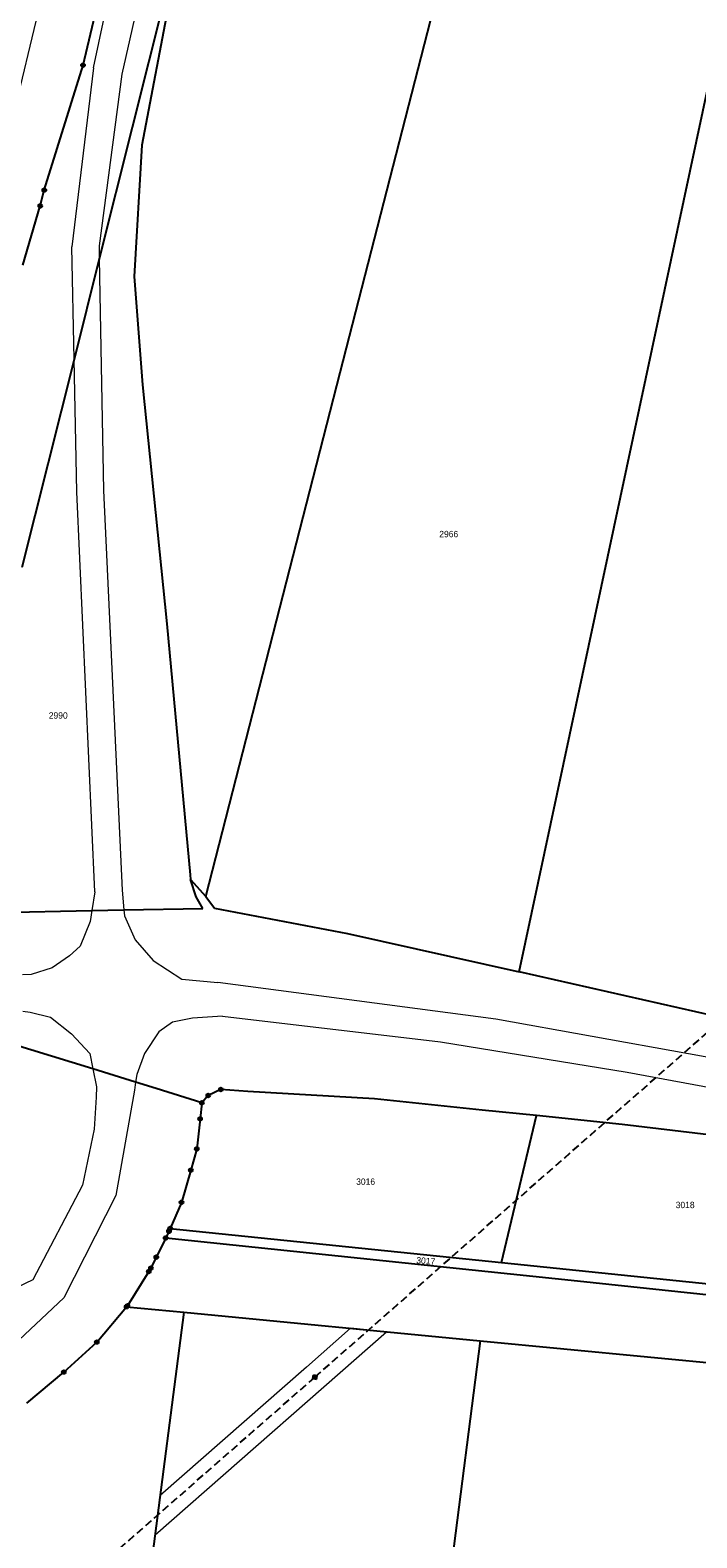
# Model space of a CAD drawing. Extents: x -606517 to -602431, y -1183120 to -1179397.
# Drawn here: x -604805.8 to -604627.6, y -1182528.7 to -1182125.3 of the extents above; entities that cross this region are included whole.
import ezdxf

# ---------------------------------------------------------------- set-up
doc = ezdxf.new("R2010")
doc.units = 0
doc.header["$LTSCALE"] = 0.68
doc.linetypes.add('MEDIUM_DASHED', pattern=[4.5, 3, -1.5])
for name, color, linetype, lineweight in [('1', 7, 'Continuous', 25), ('13', 7, 'Continuous', 13), ('4', 7, 'Continuous', 13), ('6', 7, 'Continuous', 25), ('8', 7, 'Continuous', 25)]:
    doc.layers.add(name, color=color, linetype=linetype, lineweight=lineweight)
doc.layers.add('2', color=7, linetype='Continuous')

msp = doc.modelspace()

# ---------------------------------------------------------------- linework, layer by layer
at = {"layer": '1'}
for p, q in [((-604722.94, -1182216.85), (-604687.02, -1182076.6)), ((-604791.72, -1182134.66), (-604782.46, -1182095.61)), ((-604765.78, -1182100.31), (-604787.38, -1182186.5)), ((-604765.48, -1182100.4), (-604775.96, -1182156.06)), ((-604648.04, -1182250.24), (-604620.95, -1182123.2)), ((-604802.07, -1182168.08), (-604791.72, -1182134.66)), ((-604775.96, -1182156.06), (-604778.06, -1182191.22)), ((-604803.16, -1182172.33), (-604802.07, -1182168.08)), ((-604807.79, -1182188.19), (-604803.16, -1182172.33)), ((-604787.38, -1182186.5), (-604794.11, -1182213.39)), ((-604778.06, -1182191.22), (-604775.78, -1182220.23)), ((-604794.11, -1182213.39), (-604808.07, -1182269.09)), ((-604758.86, -1182357.1), (-604722.94, -1182216.85)), ((-604775.78, -1182220.23), (-604769.29, -1182284.11)), ((-604675.13, -1182377.28), (-604648.04, -1182250.24)), ((-604769.29, -1182284.11), (-604763.08, -1182351.29)), ((-604763.08, -1182351.29), (-604762.97, -1182352.51)), ((-604761.51, -1182357.16), (-604762.97, -1182352.51)), ((-604762.97, -1182352.51), (-604758.86, -1182357.1)), ((-604759.68, -1182360.28), (-604761.51, -1182357.16)), ((-604758.86, -1182357.1), (-604756.6, -1182360.22)), ((-604814.45, -1182361.33), (-604789.32, -1182360.85)), ((-604789.32, -1182360.85), (-604780.77, -1182360.68)), ((-604780.77, -1182360.68), (-604759.68, -1182360.28)), ((-604756.6, -1182360.22), (-604721.02, -1182366.95)), ((-604721.02, -1182366.95), (-604675.13, -1182377.28)), ((-604601.13, -1182393.97), (-604675.13, -1182377.28)), ((-604789.11, -1182403.23), (-604811.16, -1182396.39)), ((-604777.66, -1182406.78), (-604789.11, -1182403.23)), ((-604772.17, -1182408.48), (-604777.66, -1182406.78)), ((-604759.93, -1182412.28), (-604772.17, -1182408.48)), ((-604754.87, -1182408.73), (-604758.24, -1182410.33)), ((-604747.66, -1182409.23), (-604754.87, -1182408.73)), ((-604713.81, -1182411.27), (-604747.66, -1182409.23)), ((-604759.93, -1182412.28), (-604760.42, -1182416.59)), ((-604758.24, -1182410.33), (-604759.93, -1182412.28)), ((-604684.96, -1182414.24), (-604713.81, -1182411.27)), ((-604760.42, -1182416.59), (-604761.3, -1182424.64)), ((-604670.44, -1182415.73), (-604684.96, -1182414.24)), ((-604679.86, -1182455.04), (-604670.44, -1182415.73)), ((-604647.53, -1182418.09), (-604670.44, -1182415.73)), ((-604606.24, -1182423.1), (-604647.53, -1182418.09)), ((-604761.3, -1182424.64), (-604762.89, -1182430.33)), ((-604762.89, -1182430.33), (-604765.39, -1182438.92)), ((-604765.39, -1182438.92), (-604768.42, -1182445.93)), ((-604768.42, -1182445.93), (-604768.74, -1182446.67)), ((-604768.42, -1182445.93), (-604679.86, -1182455.04)), ((-604769.62, -1182448.47), (-604772.13, -1182453.59)), ((-604768.74, -1182446.67), (-604769.62, -1182448.47)), ((-604659.54, -1182460.04), (-604769.62, -1182448.47)), ((-604772.13, -1182453.59), (-604773.56, -1182456.53)), ((-604774.13, -1182457.44), (-604779.85, -1182466.62)), ((-604773.56, -1182456.53), (-604774.13, -1182457.44)), ((-604679.86, -1182455.04), (-604596.72, -1182463.59)), ((-604549.45, -1182471.62), (-604659.54, -1182460.04)), ((-604788.05, -1182476.32), (-604780.06, -1182466.87)), ((-604764.76, -1182468.34), (-604781.97, -1182601.69)), ((-604779.85, -1182466.62), (-604780.06, -1182466.87)), ((-604780.06, -1182466.87), (-604764.76, -1182468.34)), ((-604764.76, -1182468.34), (-604685.5, -1182475.94)), ((-604796.84, -1182484.35), (-604788.05, -1182476.32)), ((-604685.5, -1182475.94), (-604700.64, -1182593.25)), ((-604685.5, -1182475.94), (-604568.08, -1182487.2)), ((-604806.77, -1182492.62), (-604796.84, -1182484.35))]:
    msp.add_line(p, q, dxfattribs=at)
at = {"layer": '13'}
msp.add_lwpolyline([(-604771.09, -1182517.35), (-604772.44, -1182527.86), (-604727.37, -1182488.28), (-604710.6, -1182473.53), (-604720.16, -1182472.62), (-604731.99, -1182483.02)], close=True, dxfattribs=at)
at = {"layer": '4'}
for p, q in [((-604794.45, -1182081.46), (-604811.14, -1182151.18)), ((-604788.9, -1182135.4), (-604780.53, -1182096.1)), ((-604788.9, -1182135.4), (-604794.72, -1182183.29)), ((-604781.36, -1182137.03), (-604787.44, -1182182.96)), ((-604787.44, -1182182.96), (-604787.38, -1182186.5)), ((-604787.38, -1182186.5), (-604786.26, -1182248.48)), ((-604788.53, -1182355.83), (-604793.4, -1182248.8)), ((-604786.26, -1182248.48), (-604781.28, -1182355.44)), ((-604781.28, -1182355.44), (-604780.77, -1182360.68)), ((-604780.77, -1182360.68), (-604780.61, -1182362.27)), ((-604800.01, -1182376.17), (-604805.59, -1182377.92)), ((-604805.59, -1182377.92), (-604807.93, -1182378.05)), ((-604754.47, -1182389.12), (-604696.16, -1182395.94)), ((-604696.16, -1182395.94), (-604646.24, -1182404.1)), ((-604646.24, -1182404.1), (-604436.61, -1182443.22)), ((-604788.15, -1182408.01), (-604788.24, -1182410.75))]:
    msp.add_line(p, q, dxfattribs=at)
for points in [[(-604771.79, -1182094.77), (-604772.6, -1182098.36), (-604781.36, -1182137.03)], [(-604793.4, -1182248.8), (-604794.11, -1182213.39), (-604794.72, -1182183.29)], [(-604788.53, -1182355.83), (-604789.32, -1182360.85), (-604789.78, -1182363.77)], [(-604789.78, -1182363.77), (-604792.47, -1182370.38), (-604795.36, -1182372.96), (-604800.01, -1182376.17)], [(-604780.61, -1182362.27), (-604777.8, -1182368.68), (-604772.99, -1182374.18), (-604765.31, -1182379.25), (-604755.66, -1182380.1)], [(-604604.04, -1182403.79), (-604681.33, -1182389.88), (-604755.66, -1182380.1)], [(-604807.8, -1182387.79), (-604805.89, -1182388), (-604800.43, -1182389.41), (-604794.84, -1182393.83), (-604789.93, -1182399.11)], [(-604754.47, -1182389.12), (-604762.43, -1182389.64), (-604767.81, -1182390.74), (-604771.49, -1182393.31), (-604775.28, -1182399.07), (-604777.36, -1182404.7)], [(-604789.93, -1182399.11), (-604789.11, -1182403.23), (-604788.15, -1182408.01)], [(-604777.36, -1182404.7), (-604777.66, -1182406.78), (-604777.96, -1182408.91)], [(-604777.96, -1182408.91), (-604782.95, -1182437.12), (-604796.84, -1182464.47), (-604819.35, -1182485.58)], [(-604788.24, -1182410.75), (-604788.77, -1182419.35), (-604791.87, -1182434.32)], [(-604791.87, -1182434.32), (-604805.13, -1182459.7), (-604828.46, -1182470.84)]]:
    msp.add_lwpolyline(points, dxfattribs=at)
at = {"layer": '6'}
for p, q in [((-604730.275, -1182486.034), (-604730.067, -1182485.056)), ((-604730.275, -1182486.034), (-604729.295, -1182486.242)), ((-604730.233, -1182485.839), (-604729.254, -1182486.047)), ((-604730.191, -1182485.643), (-604729.212, -1182485.851)), ((-604730.15, -1182485.447), (-604729.171, -1182485.655)), ((-604730.108, -1182485.252), (-604729.129, -1182485.46)), ((-604730.078, -1182486.076), (-604729.87, -1182485.098)), ((-604730.067, -1182485.056), (-604729.087, -1182485.264)), ((-604729.883, -1182486.117), (-604729.675, -1182485.139)), ((-604729.687, -1182486.159), (-604729.479, -1182485.181)), ((-604729.492, -1182486.201), (-604729.284, -1182485.222)), ((-604729.295, -1182486.242), (-604729.087, -1182485.264))]:
    msp.add_line(p, q, dxfattribs=at)
at = {"layer": '6', "linetype": 'MEDIUM_DASHED'}
msp.add_lwpolyline([(-605015.62, -1182869.31), (-604910.62, -1182644.53), (-604729.68, -1182485.65), (-604552.48, -1182329.87)], dxfattribs=at)
at = {"layer": '8'}
for centre, radius in [((-604791.72, -1182134.6599), 0.5), ((-604791.72, -1182134.6599), 0.0303), ((-604802.07, -1182168.0799), 0.5), ((-604802.07, -1182168.0799), 0.0303), ((-604803.16, -1182172.3299), 0.5), ((-604803.16, -1182172.3299), 0.0303), ((-604754.87, -1182408.7299), 0.5), ((-604754.87, -1182408.7299), 0.0303), ((-604759.93, -1182412.2799), 0.5), ((-604759.93, -1182412.2799), 0.0303), ((-604758.24, -1182410.3299), 0.5), ((-604758.24, -1182410.3299), 0.0303), ((-604760.42, -1182416.5899), 0.5), ((-604760.42, -1182416.5899), 0.0303), ((-604761.3, -1182424.6399), 0.5), ((-604761.3, -1182424.6399), 0.0303), ((-604762.89, -1182430.3299), 0.5), ((-604762.89, -1182430.3299), 0.0303), ((-604765.39, -1182438.9199), 0.5), ((-604765.39, -1182438.9199), 0.0303), ((-604768.42, -1182445.9299), 0.5), ((-604768.42, -1182445.9299), 0.0303), ((-604769.62, -1182448.4699), 0.5), ((-604769.62, -1182448.4699), 0.0303), ((-604768.74, -1182446.6699), 0.5), ((-604768.74, -1182446.6699), 0.0303), ((-604772.13, -1182453.5899), 0.5), ((-604772.13, -1182453.5899), 0.0303), ((-604774.13, -1182457.4399), 0.5), ((-604774.13, -1182457.4399), 0.0303), ((-604773.56, -1182456.5299), 0.5), ((-604773.56, -1182456.5299), 0.0303), ((-604779.85, -1182466.6199), 0.5), ((-604780.06, -1182466.8699), 0.5), ((-604780.06, -1182466.8699), 0.0303), ((-604779.85, -1182466.6199), 0.0303), ((-604788.05, -1182476.3199), 0.5), ((-604788.05, -1182476.3199), 0.0303), ((-604796.84, -1182484.3499), 0.5), ((-604796.84, -1182484.3499), 0.0303)]:
    msp.add_circle(centre, radius, dxfattribs=at)

# ---------------------------------------------------------------- texts
at = {"layer": '2'}
for s, p in [('2966', (-604696.47, -1182260.965)), ('2990', (-604800.87, -1182309.505)), ('3016', (-604718.69, -1182434.235)), ('3018', (-604633.26, -1182440.475))]:
    msp.add_text(s, height=1.7, dxfattribs=at).set_placement(p)
msp.add_text('3017', height=1.7, rotation=355, dxfattribs=at).set_placement((-604702.667, -1182455.213))

doc.saveas('drawing.dxf')
